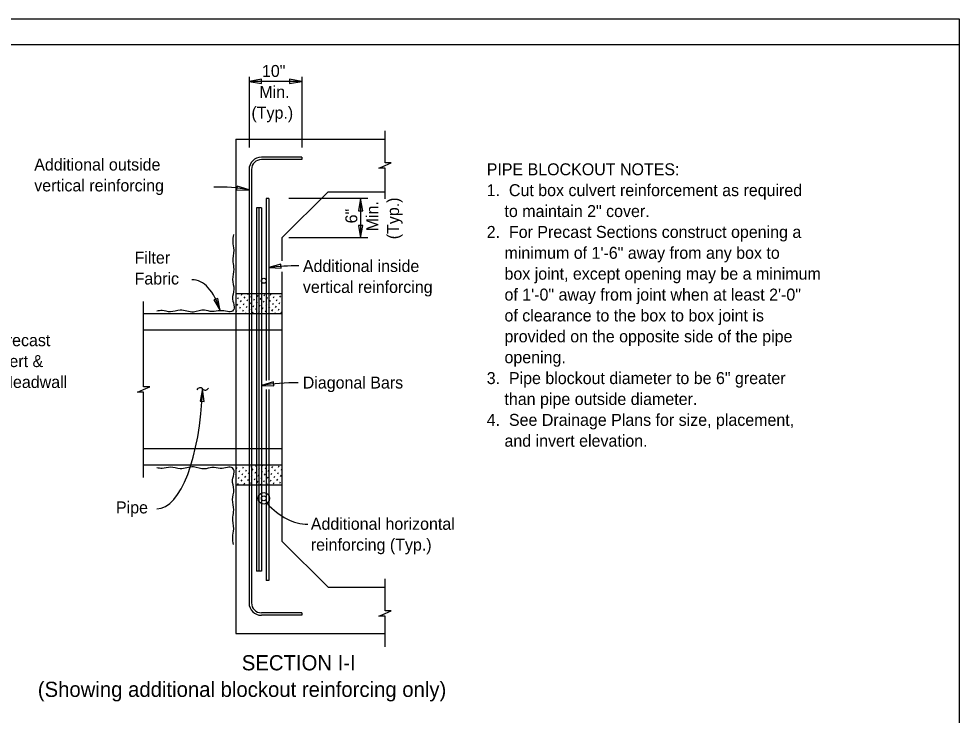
# Model space of a CAD drawing. Extents: x 0 to 30.8, y 0 to 19.8.
# Drawn here: x 18.91 to 30.8, y 11 to 19.8 of the extents above; entities that cross this region are included whole.
import ezdxf

# ---------------------------------------------------------------- set-up
doc = ezdxf.new("R2010")
doc.units = 0
for name, color, linetype in [('Dimension', 7, 'Continuous'), ('Miscellaneous', 7, 'Continuous'), ('Miscellaneous1', 7, 'Continuous'), ('Rebar', 7, 'Continuous'), ('SubStrConc', 7, 'Continuous'), ('SubStrConc_h', 7, 'Continuous'), ('TextStructures', 7, 'Continuous')]:
    doc.layers.add(name, color=color, linetype=linetype)

msp = doc.modelspace()

# ---------------------------------------------------------------- linework, layer by layer
at = {"layer": 'Dimension'}
for p, q in [((21.818, 19.067), (21.818, 18.172)), ((22.484, 19.067), (22.484, 18.172)), ((22.484, 19.009), (21.818, 19.009)), ((23.32, 17.53), (22.323, 17.53)), ((23.229, 17.53), (23.229, 17.03)), ((23.32, 17.03), (22.323, 17.03)), ((21.818, 12.965), (21.818, 12.965))]:
    msp.add_line(p, q, dxfattribs=at)
for points in [[(21.818, 19.009), (21.974, 18.983), (21.974, 19.035)], [(22.484, 19.009), (22.328, 19.035), (22.328, 18.983)], [(21.818, 17.639), (21.666, 17.686), (21.659, 17.634)], [(23.229, 17.53), (23.202, 17.374), (23.255, 17.374)], [(23.229, 17.03), (23.255, 17.186), (23.202, 17.186)], [(22.068, 16.655), (22.226, 16.646), (22.22, 16.698)], [(21.453, 16.111), (21.421, 16.266), (21.372, 16.247)], [(21.231, 15.121), (21.199, 14.966), (21.252, 14.964)], [(21.974, 15.165), (22.132, 15.158), (22.125, 15.211)]]:
    msp.add_lwpolyline(points, close=True, dxfattribs=at)
for points in [[(23.538, 17.526), (23.538, 17.913), (23.46, 17.913), (23.538, 17.947), (23.615, 17.981), (23.538, 17.981), (23.538, 18.385)], [(20.484, 14.001), (20.484, 15.08), (20.407, 15.08), (20.484, 15.113), (20.562, 15.147), (20.484, 15.147), (20.484, 16.228)], [(23.538, 11.859), (23.538, 12.246), (23.46, 12.246), (23.538, 12.28), (23.615, 12.314), (23.538, 12.314), (23.538, 12.719)]]:
    msp.add_lwpolyline(points, dxfattribs=at)
msp.add_circle((22.005, 13.738), 0.0727, dxfattribs=at)
for centre, radius, start, end in [((21.417, 15.302), 2.371, 80.2835, 91.0738), ((22.389, 14.177), 2.499, 88.6532, 97.401), ((21.198, 15.091), 0.0447, 41.8752, 153.6025), ((21.264, 15.151), 0.0447, 221.8752, 333.6025), ((22.376, 12.684), 2.513, 88.5996, 99.2102)]:
    msp.add_arc(centre, radius, start, end, dxfattribs=at)
for centre, major_axis, ratio, start_param, end_param in [((21.107, 15.733), (0.011, -0.769), 0.521756, 2.076946, 3.141593), ((20.577, 15.529), (-0.073, 1.925), 0.340061, 3.141593, 4.485805), ((22.542, 16), (-0.018, 2.588), 0.448909, 2.682262, 3.141593)]:
    msp.add_ellipse(centre, major_axis=major_axis, ratio=ratio, start_param=start_param, end_param=end_param, dxfattribs=at)
at = {"layer": 'Miscellaneous'}
for p, q in [((21.721, 16.306), (21.73, 16.322)), ((21.804, 16.316), (21.808, 16.322)), ((21.841, 16.279), (21.85, 16.296)), ((21.924, 16.289), (21.933, 16.306)), ((22.007, 16.299), (22.016, 16.315)), ((22.09, 16.308), (22.097, 16.322)), ((22.173, 16.318), (22.175, 16.322)), ((22.209, 16.281), (22.219, 16.298)), ((21.665, 16.177), (21.675, 16.194)), ((21.675, 16.26), (21.685, 16.277)), ((21.711, 16.223), (21.721, 16.24)), ((21.748, 16.186), (21.758, 16.203)), ((21.758, 16.269), (21.767, 16.286)), ((21.794, 16.233), (21.804, 16.25)), ((21.831, 16.196), (21.841, 16.213)), ((21.877, 16.243), (21.887, 16.259)), ((21.914, 16.206), (21.924, 16.223)), ((21.951, 16.169), (21.96, 16.186)), ((21.96, 16.252), (21.97, 16.269)), ((21.997, 16.216), (22.007, 16.232)), ((22.034, 16.179), (22.043, 16.196)), ((22.043, 16.262), (22.053, 16.279)), ((22.08, 16.225), (22.09, 16.242)), ((22.117, 16.189), (22.126, 16.206)), ((22.126, 16.272), (22.136, 16.288)), ((22.163, 16.235), (22.173, 16.252)), ((22.2, 16.198), (22.209, 16.215)), ((21.655, 16.094), (21.665, 16.111)), ((21.7, 16.072), (21.702, 16.074)), ((21.702, 16.14), (21.711, 16.157)), ((21.738, 16.103), (21.748, 16.12)), ((21.778, 16.072), (21.785, 16.084)), ((21.785, 16.15), (21.794, 16.167)), ((21.821, 16.113), (21.831, 16.13)), ((21.858, 16.077), (21.868, 16.093)), ((21.868, 16.16), (21.877, 16.176)), ((21.904, 16.123), (21.914, 16.14)), ((21.941, 16.086), (21.951, 16.103)), ((21.987, 16.133), (21.997, 16.149)), ((22.024, 16.096), (22.034, 16.113)), ((22.068, 16.072), (22.07, 16.076)), ((22.07, 16.142), (22.08, 16.159)), ((22.107, 16.106), (22.117, 16.123)), ((22.145, 16.072), (22.153, 16.086)), ((22.153, 16.152), (22.163, 16.169)), ((22.19, 16.115), (22.2, 16.132)), ((22.226, 16.079), (22.234, 16.092)), ((21.905, 14.139), (21.914, 14.155)), ((21.988, 14.149), (21.992, 14.155)), ((21.651, 14.035), (21.656, 14.044)), ((21.656, 14.11), (21.666, 14.127)), ((21.693, 14.073), (21.702, 14.09)), ((21.729, 14.036), (21.739, 14.053)), ((21.739, 14.119), (21.749, 14.136)), ((21.776, 14.083), (21.785, 14.1)), ((21.812, 14.046), (21.822, 14.063)), ((21.822, 14.129), (21.832, 14.146)), ((21.859, 14.093), (21.868, 14.109)), ((21.895, 14.056), (21.905, 14.073)), ((21.932, 14.019), (21.942, 14.036)), ((21.942, 14.102), (21.951, 14.119)), ((21.978, 14.066), (21.988, 14.082)), ((22.015, 14.029), (22.025, 14.046)), ((22.025, 14.112), (22.034, 14.129)), ((22.061, 14.075), (22.071, 14.092)), ((22.098, 14.039), (22.108, 14.056)), ((22.108, 14.122), (22.117, 14.139)), ((22.144, 14.085), (22.154, 14.102)), ((22.181, 14.048), (22.191, 14.065)), ((22.191, 14.131), (22.2, 14.148)), ((22.227, 14.095), (22.234, 14.107)), ((21.673, 13.907), (21.683, 13.924)), ((21.683, 13.99), (21.693, 14.007)), ((21.72, 13.953), (21.729, 13.97)), ((21.756, 13.917), (21.766, 13.934)), ((21.766, 14), (21.776, 14.017)), ((21.803, 13.963), (21.812, 13.98)), ((21.839, 13.927), (21.849, 13.943)), ((21.849, 14.01), (21.859, 14.026)), ((21.886, 13.973), (21.895, 13.99)), ((21.922, 13.936), (21.932, 13.953)), ((21.962, 13.905), (21.969, 13.916)), ((21.969, 13.983), (21.978, 13.999)), ((22.005, 13.946), (22.015, 13.963)), ((22.042, 13.909), (22.052, 13.926)), ((22.052, 13.992), (22.061, 14.009)), ((22.088, 13.956), (22.098, 13.973)), ((22.125, 13.919), (22.135, 13.936)), ((22.135, 14.002), (22.144, 14.019)), ((22.171, 13.965), (22.181, 13.982)), ((22.208, 13.929), (22.217, 13.946)), ((22.217, 14.012), (22.227, 14.029)), ((21.885, 13.905), (21.886, 13.907))]:
    msp.add_line(p, q, dxfattribs=at)
for points in [[(21.62, 17.072), (21.612, 16.984), (21.624, 16.876), (21.612, 16.727), (21.625, 16.635), (21.609, 16.505), (21.626, 16.381), (21.609, 16.257), (21.629, 16.156), (21.609, 16.105), (21.546, 16.098), (21.454, 16.11), (21.348, 16.098), (21.254, 16.118), (21.116, 16.093), (20.945, 16.116), (20.825, 16.095), (20.718, 16.112), (20.651, 16.103)], [(21.62, 13.155), (21.612, 13.243), (21.624, 13.351), (21.612, 13.5), (21.625, 13.592), (21.609, 13.722), (21.626, 13.846), (21.609, 13.97), (21.629, 14.071), (21.609, 14.122), (21.546, 14.129), (21.454, 14.116), (21.348, 14.129), (21.254, 14.109), (21.116, 14.134), (20.945, 14.111), (20.825, 14.132), (20.718, 14.115), (20.651, 14.124)]]:
    msp.add_spline(points, degree=3, dxfattribs=at)
at = {"layer": 'Miscellaneous1'}
msp.add_lwpolyline([(0, 19.8), (30.8, 19.8), (30.8, 0), (0, 0)], close=True, dxfattribs=at)
at = {"layer": 'Rebar'}
for p, q in [((22.484, 18.051), (21.974, 18.051)), ((22.484, 18.02), (21.974, 18.02)), ((22.484, 18.051), (22.484, 18.02)), ((21.818, 17.895), (21.818, 12.415)), ((21.849, 17.895), (21.849, 12.415)), ((22.068, 17.53), (22.036, 17.53)), ((22.036, 17.53), (22.036, 15.228)), ((22.068, 17.53), (22.068, 15.231)), ((21.974, 17.412), (21.912, 17.412)), ((21.912, 17.412), (21.912, 12.815)), ((21.943, 17.412), (21.943, 12.815)), ((21.974, 17.412), (21.974, 12.815)), ((22.036, 15.112), (22.036, 12.697)), ((22.068, 15.112), (22.068, 12.697)), ((21.974, 12.815), (21.912, 12.815)), ((22.068, 12.697), (22.036, 12.697)), ((22.484, 12.29), (21.974, 12.29)), ((22.484, 12.259), (21.974, 12.259)), ((22.484, 12.29), (22.484, 12.259))]:
    msp.add_line(p, q, dxfattribs=at)
for centre in [(22.005, 16.488), (22.005, 13.738)]:
    msp.add_circle(centre, 0.0312, dxfattribs=at)
for centre, radius, start, end in [((21.974, 17.895), 0.156, 90.0001, 179.9999), ((21.974, 17.895), 0.125, 90, 180), ((21.974, 12.415), 0.156, 180.0001, 269.9999), ((21.974, 12.415), 0.125, 180, 270)]:
    msp.add_arc(centre, radius, start, end, dxfattribs=at)
at = {"layer": 'SubStrConc'}
for p, q in [((21.651, 18.28), (21.651, 12.03)), ((21.651, 18.28), (23.538, 18.28)), ((22.234, 17.03), (22.818, 17.613)), ((22.818, 17.613), (23.538, 17.613)), ((22.234, 17.03), (22.234, 16.74)), ((22.234, 16.603), (22.234, 13.197)), ((22.234, 16.322), (21.651, 16.322)), ((22.234, 16.072), (20.484, 16.072)), ((22.234, 14.155), (20.484, 14.155)), ((22.234, 13.905), (21.651, 13.905)), ((22.234, 13.197), (22.818, 12.613)), ((22.818, 12.613), (23.538, 12.613)), ((21.651, 12.03), (23.538, 12.03))]:
    msp.add_line(p, q, dxfattribs=at)
at = {"layer": 'SubStrConc_h'}
for p, q in [((22.234, 15.863), (20.484, 15.863)), ((22.234, 14.363), (20.484, 14.363))]:
    msp.add_line(p, q, dxfattribs=at)
at = {"layer": 'TextStructures'}
msp.add_lwpolyline([(0, 19.477), (30.8, 19.477), (30.8, 0), (0, 0)], close=True, dxfattribs=at)

# ---------------------------------------------------------------- texts
at = {"layer": 'Dimension'}
for s, height, p in [('10"', 0.1512, (21.981, 19.065)), ('Min.', 0.1512, (21.948, 18.801)), ('(Typ.)', 0.1512, (21.848, 18.537)), ('Additional outside', 0.1512, (19.101, 17.882)), ('PIPE BLOCKOUT NOTES:', 0.1512, (24.824, 17.822)), ('vertical reinforcing', 0.1512, (19.101, 17.618)), ('1.  Cut box culvert reinforcement as required', 0.1512, (24.824, 17.558)), ('    to maintain 2" cover.', 0.1512, (24.824, 17.294)), ('2.  For Precast Sections construct opening a', 0.1512, (24.824, 17.03)), ('    minimum of 1\'-6" away from any box to', 0.1512, (24.824, 16.766)), ('Filter', 0.1512, (20.37, 16.705)), ('Additional inside', 0.1512, (22.499, 16.599)), ('    box joint, except opening may be a minimum', 0.1512, (24.824, 16.502)), ('Fabric', 0.1512, (20.37, 16.441)), ('vertical reinforcing', 0.1512, (22.499, 16.335)), ('    of 1\'-0" away from joint when at least 2\'-0"', 0.1512, (24.824, 16.238)), ('    of clearance to the box to box joint is', 0.1512, (24.824, 15.974)), ('End of Precast', 0.1512, (17.978, 15.661)), ('    provided on the opposite side of the pipe', 0.1512, (24.824, 15.71)), ('    opening.', 0.1512, (24.824, 15.446)), ('Box Culvert &', 0.1512, (17.978, 15.397)), ('back of Headwall', 0.1512, (17.978, 15.133)), ('3.  Pipe blockout diameter to be 6" greater', 0.1512, (24.824, 15.182)), ('    than pipe outside diameter.', 0.1512, (24.824, 14.918)), ('4.  See Drainage Plans for size, placement,', 0.1512, (24.824, 14.654)), ('    and invert elevation.', 0.1512, (24.824, 14.39)), ('Additional horizontal', 0.1512, (22.599, 13.34)), ('reinforcing (Typ.)', 0.1512, (22.599, 13.076)), ('SECTION I-I', 0.192, (21.726, 11.563)), ('(Showing additional blockout reinforcing only)', 0.192, (19.146, 11.227))]:
    msp.add_text(s, height=height, dxfattribs=at).set_placement(p)
for s, p in [('(Typ.)', (23.715, 17.013)), ('6"', (23.187, 17.214)), ('Min.', (23.451, 17.113))]:
    msp.add_text(s, height=0.1512, rotation=90, dxfattribs=at).set_placement(p)
at = {"layer": 'TextStructures'}
for s, p in [('Diagonal Bars', (22.497, 15.126)), ('Pipe', (20.135, 13.547))]:
    msp.add_text(s, height=0.1512, dxfattribs=at).set_placement(p)

doc.saveas('drawing.dxf')
